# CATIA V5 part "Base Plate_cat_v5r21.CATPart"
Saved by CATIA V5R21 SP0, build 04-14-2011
Part number: Base Plate
Bounding box of the stored display mesh (mm): x -10 to 10, y 0 to 144, z 0 to 6
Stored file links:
  D:\CATIA V5R21 E-RESOURCES\CATIA-V5R21\catia-v5r21-Tut\c13-catia-v5r21-tut\c13-catia-v5r21-tut02\Bench Vice\Base Plate_cat_v5r21.CATPart
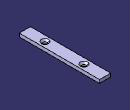
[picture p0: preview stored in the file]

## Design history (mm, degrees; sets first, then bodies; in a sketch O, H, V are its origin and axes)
Body1 (main body)
  Sketch1 on zx-plane, origin (0, 0, 0), H (-1, 0, 0), V (0, 0, 1)
    point P1 (-10, 0)
    line L1 (-10, 0) -> (10, 0)
    line L2 (10, 0) -> (10, 6)
    line L3 (10, 6) -> (-10, 6)
    line L4 (-10, 6) -> (-10, 0)
    length L3 = 20
    length L2 = 6
    distance V L2 = 10
    coincidence: P1 H
    horizontal: L1 H, L3 H
    vertical: L2 V, L4 V
  Pad1: profile Sketch1, direction (0, 1, 0), length 144
  Sketch2 on face of Pad1, origin (-6.0071, 115.251, 6), H (1, 0, 0), V (0, 1, 0)
    point P1 (6.0071, -9.251)
    reference projected line E1 (-3.9929, -115.251) -> (-3.9929, 28.749) from edge of Pad1
    reference projected line E2 (16.0071, 28.749) -> (-3.9929, 28.749) from edge of Pad1
    distance E1 P1 = 10
    distance E2 P1 = 38
  Hole1: placed by Sketch2, at (0, 106, 6) direction (0, 0, -1), diameter 7, through (limit type 6), countersink depth 3, countersink angle 90
  RectPattern1: of Hole1, direction 1 instances 2, spacing 70, along edge of Pad1 reversed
